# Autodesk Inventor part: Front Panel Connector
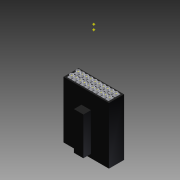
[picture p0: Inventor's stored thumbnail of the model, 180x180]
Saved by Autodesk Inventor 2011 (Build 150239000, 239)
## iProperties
Created: 2005-12
Part Number: Front Panel Connector
Document SubType Name: Modeling
Designer: Simon.Ng@autodesk.com
Stock Number: config - c9g5 connector
Density: 1 g/cm^3
Categories: <MemberInstance><Categories><Category DisplayName="" Mnemonic="CABLEANDHARNESS" InternalName="e4a7e005-5e42-4d16-b293-125e7f0d0512"><Category DisplayName="" Mne
Mass: 0.35267 g
Surface Area: 21.3815 cm^2
Volume: 0.35267 cm^3
GlobalPropertyList: <PropertyList/>
Company: Autodesk Asia Pte. Ltd.
Title: PC Demo
Author: Simon.Ng@autodesk.com
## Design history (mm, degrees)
sketch "Sketch3"
  geometry: L1 (7, -7)-(0, -7); L2 (9.5, 2.9)-(9.5, -8.3); L3 (3.5, -2.5)-(15.5, -2.5); L4 (15.5, -2.5)-(15.5, -6.5); L5 (15.5, -6.5)-(3.5, -6.5); L6 (3.5, -6.5)-(3.5, -2.5)
  constraints: 12 end point, 2 parallel, 1 horizontal, 1 perpendicular, 1 other
  dimensions: "d8" = 12 distance of L3.start L3.end; "d9" = 4 distance of L5.end L3.start; "d10" = 0.5 distance between parallel lines of L1 L5
extrude "Extrusion3" join sketch "Sketch3" distance "d11" = 15; taper "d12" = 0 deg
sketch "Sketch4"
  geometry: L1 (15.5, -2.5)-(15.5, -6.5) reference; L2 (3.5, -2.5)-(15.5, -2.5) reference; L3 (15.5, -6.5)-(3.5, -6.5) reference; L4 (15, -2.9)-(14, -2.9); L5 (14, -2.9)-(14, -4.4); L6 (14, -4.4)-(15, -4.4); L7 (15, -4.4)-(15, -2.9); L8 (15, -4.6)-(14, -4.6); L9 (14, -4.6)-(14, -6.1); L10 (14, -6.1)-(15, -6.1); L11 (15, -6.1)-(15, -4.6)
  constraints: 16 end point, 4 parallel, 3 collinear, 2 horizontal, 2 perpendicular
  dimensions: "d13" = 1 distance of L4.start L4.end; "d14" = 0.5 distance between parallel lines of L1 L7; "d15" = 0.4 distance between parallel lines of L4 L2; "d16" = 0.4 distance between parallel lines of L3 L10; "d17" = 1.5 distance of L4.end L5.end
extrude "Extrusion4" cut sketch "Sketch4" distance "d18" = 14; taper "d19" = 0 deg
sketch "Sketch5"
  geometry: L1 (14, -6.1)-(14, -4.6) reference; L2 (15, -4.6)-(15, -6.1) reference; L3 (15, -6.1)-(14, -6.1) reference; L4 (14, -4.4)-(14, -2.9) reference; L5 (14, -2.9)-(15, -2.9) reference; L6 (15, -2.9)-(15, -4.4) reference; L7 (14, -3.65)-(15, -3.65); L8 (14, -5.35)-(15, -5.35); L9 (14.5, -2.9)-(14.5, -6.1); C1 r 0.45 at (14.5, -3.65); C2 r 0.4 at (14.5, -3.65); C3 r 0.45 at (14.5, -5.35); C4 r 0.4 at (14.5, -5.35)
  constraints: 8 midpoint, 6 end point, 4 centre point, 2 coincident, 2 equal radius, 2 point on line
  dimensions: "d20" = 0.8 diameter of C2; "d21" = 0.05 radial gap between concentric circles of C2 C1
extrude "Extrusion5" join sketch "Sketch5" stored distance "d22" = 1; taper "d23" = 0 deg
pattern_linear "Rectangular Pattern1"
sketch "Sketch6"
  geometry: L1 (4.75, -4)-(7.25, -4); L2 (7.25, -4)-(7.25, -14); L3 (7.25, -14)-(4.75, -14); L4 (4.75, -14)-(4.75, -4); L5 (6, -4)-(6, -14); L6 (12, -15)-(0, -15) reference; 1 further point
  constraints: 10 end point, 3 midpoint, 2 parallel, 1 horizontal, 1 perpendicular, 1 vertical alignment
  dimensions: "d28" = 2.5 distance of L2.end L3.end; "d29" = 10 distance of L3.end L1.start
extrude "Extrusion6" join sketch "Sketch6" distance "d30" = 2; taper "d31" = 0 deg
sketch "Sketch7"
  geometry: L1 (4, -6.1)-(4, -4.6) reference; L2 (4, -4.6)-(5, -4.6) reference; L3 (5, -4.6)-(5, -6.1) reference; L4 (5, -6.1)-(4, -6.1) reference; L5 (4, -4.4)-(4, -2.9) reference; L6 (4, -2.9)-(5, -2.9) reference; L7 (5, -2.9)-(5, -4.4) reference; L8 (5, -4.4)-(4, -4.4) reference; L9 (5.111, -6.1)-(5.111, -4.6) reference; L10 (5.111, -4.6)-(6.111, -4.6) reference; L11 (6.111, -4.6)-(6.111, -6.1) reference; L12 (6.111, -6.1)-(5.111, -6.1) reference; L13 (5.111, -4.4)-(5.111, -2.9) reference; L14 (5.111, -2.9)-(6.111, -2.9) reference; L15 (6.111, -2.9)-(6.111, -4.4) reference; L16 (6.111, -4.4)-(5.111, -4.4) reference; L17 (6.222, -6.1)-(6.222, -4.6) reference; L18 (6.222, -4.6)-(7.222, -4.6) reference; L19 (7.222, -4.6)-(7.222, -6.1) reference; L20 (7.222, -6.1)-(6.222, -6.1) reference; L21 (6.222, -4.4)-(6.222, -2.9) reference; L22 (6.222, -2.9)-(7.222, -2.9) reference; L23 (7.222, -2.9)-(7.222, -4.4) reference; L24 (7.222, -4.4)-(6.222, -4.4) reference; L25 (7.333, -6.1)-(7.333, -4.6) reference; L26 (7.333, -4.6)-(8.333, -4.6) reference; L27 (8.333, -4.6)-(8.333, -6.1) reference; L28 (8.333, -6.1)-(7.333, -6.1) reference; L29 (7.333, -4.4)-(7.333, -2.9) reference; L30 (7.333, -2.9)-(8.333, -2.9) reference; L31 (8.333, -2.9)-(8.333, -4.4) reference; L32 (8.333, -4.4)-(7.333, -4.4) reference; L33 (8.444, -6.1)-(8.444, -4.6) reference; L34 (8.444, -4.6)-(9.444, -4.6) reference; L35 (9.444, -4.6)-(9.444, -6.1) reference; L36 (9.444, -6.1)-(8.444, -6.1) reference; L37 (8.444, -4.4)-(8.444, -2.9) reference; L38 (8.444, -2.9)-(9.444, -2.9) reference; L39 (9.444, -2.9)-(9.444, -4.4) reference; L40 (9.444, -4.4)-(8.444, -4.4) reference; L41 (9.556, -6.1)-(9.556, -4.6) reference; L42 (9.556, -4.6)-(10.556, -4.6) reference; L43 (10.556, -4.6)-(10.556, -6.1) reference; L44 (10.556, -6.1)-(9.556, -6.1) reference; L45 (9.556, -4.4)-(9.556, -2.9) reference; L46 (9.556, -2.9)-(10.556, -2.9) reference; L47 (10.556, -2.9)-(10.556, -4.4) reference; L48 (10.556, -4.4)-(9.556, -4.4) reference; L49 (10.667, -6.1)-(10.667, -4.6) reference; L50 (10.667, -4.6)-(11.667, -4.6) reference; L51 (11.667, -4.6)-(11.667, -6.1) reference; L52 (11.667, -6.1)-(10.667, -6.1) reference; L53 (10.667, -4.4)-(10.667, -2.9) reference; L54 (10.667, -2.9)-(11.667, -2.9) reference; L55 (11.667, -2.9)-(11.667, -4.4) reference; L56 (11.667, -4.4)-(10.667, -4.4) reference; L57 (11.778, -6.1)-(11.778, -4.6) reference; L58 (11.778, -4.6)-(12.778, -4.6) reference; L59 (12.778, -4.6)-(12.778, -6.1) reference; L60 (12.778, -6.1)-(11.778, -6.1) reference; L61 (11.778, -4.4)-(11.778, -2.9) reference; L62 (11.778, -2.9)-(12.778, -2.9) reference; L63 (12.778, -2.9)-(12.778, -4.4) reference; L64 (12.778, -4.4)-(11.778, -4.4) reference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; C1 r 0.4 at (14.5, -5.35) reference; C2 r 0.4 at (13.389, -5.35) reference; C3 r 0.4 at (12.278, -5.35) reference; C4 r 0.4 at (11.167, -5.35) reference; C5 r 0.4 at (10.056, -5.35) reference; C6 r 0.4 at (8.944, -5.35) reference; C7 r 0.4 at (7.833, -5.35) reference; C8 r 0.4 at (6.722, -5.35) reference; C9 r 0.4 at (5.611, -5.35) reference; C10 r 0.4 at (4.5, -5.35) reference; C11 r 0.4 at (4.5, -3.65) reference; C12 r 0.4 at (5.611, -3.65) reference; C13 r 0.4 at (6.722, -3.65) reference; C14 r 0.4 at (7.833, -3.65) reference; C15 r 0.4 at (8.944, -3.65) reference; C16 r 0.4 at (10.056, -3.65) reference; C17 r 0.4 at (11.167, -3.65) reference; C18 r 0.4 at (12.278, -3.65) reference; C19 r 0.4 at (13.389, -3.65) reference; C20 r 0.4 at (14.5, -3.65) reference
node "1"
node "2"
node "3"
node "4"
node "5"
node "6"
node "7"
node "8"
node "9"
node "10"
node "11"
node "12"
node "13"
node "14"
node "15"
node "16"
node "17"
node "18"
node "19"
node "20"
workplane "Work Plane1"
workplane "Work Plane2"
sketch "Sketch8"
  geometry: L1 (4.5, -3.65)-(14.5, -5.35); C1 r 0.4 at (4.5, -3.65) reference; C2 r 0.4 at (14.5, -5.35) reference; 1 further point
  constraints: 2 end point, 1 midpoint
workpoint "Work Point21"
sketch "Sketch9"
  geometry: 1 further point
workpoint "Work Point22"
body "Solid1"
other parameters: "d32" = 12.7, "d33" = 13.97
